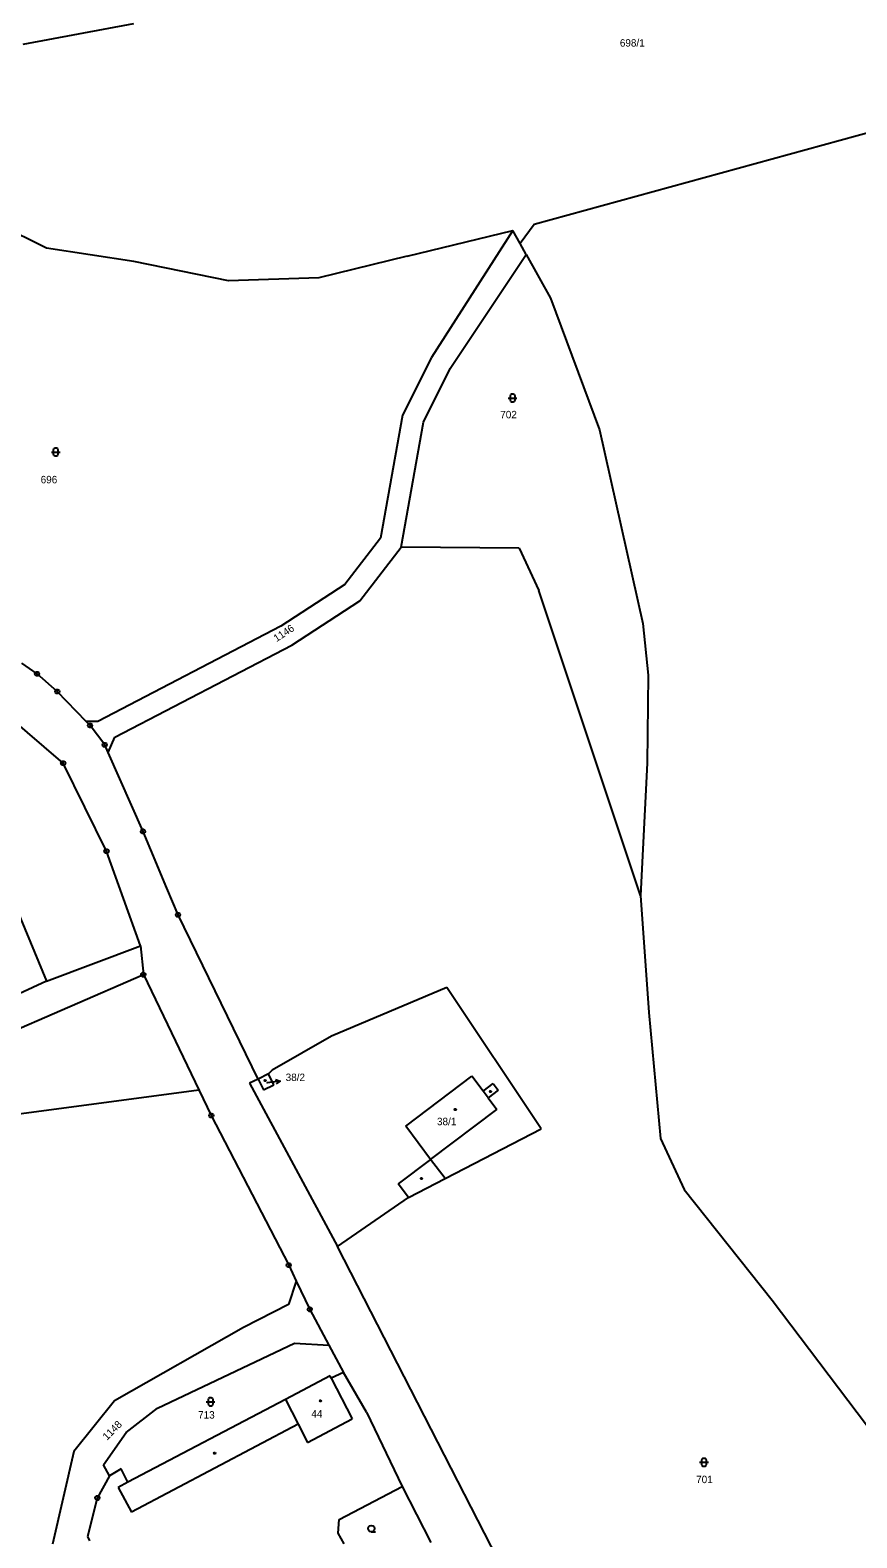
# Model space of a CAD drawing. Extents: x -812394 to -807601, y -1013098 to -1009266.
# Drawn here: x -809607.5 to -809418.3, y -1011158.1 to -1010813 of the extents above; entities that cross this region are included whole.
import ezdxf

# ---------------------------------------------------------------- set-up
doc = ezdxf.new("R2010")
doc.units = 0
for name, color, linetype in [('KN_HRANICE', 7, 'Continuous'), ('KN_KULTURY', 7, 'Continuous'), ('KN_MEZNIKY', 7, 'Continuous'), ('KN_PARCELY', 7, 'Continuous'), ('KN_SLUCKY', 7, 'Continuous'), ('KN_VEDENI', 7, 'Continuous')]:
    doc.layers.add(name, color=color, linetype=linetype)

# ---------------------------------------------------------------- blocks, each defined once
blk = doc.blocks.new('304')
blk.add_lwpolyline([(0, 0), (-0.38, 0.1), (-0.65, 0.37), (-0.75, 0.74), (-0.65, 1.11), (-0.38, 1.38), (-0.01, 1.48), (0.36, 1.38), (0.63, 1.11), (0.73, 0.73), (0.63, 0.35), (0.36, 0.08), (-0.02, -0.02), (0.98, -0.02)])
blk = doc.blocks.new('316')
for points in [[(-1, 1), (0.27, 1), (1, 1)], [(-0.5, 1.5), (-0.4, 1.79), (-0.15, 1.97), (0.16, 1.97), (0.41, 1.79), (0.51, 1.5), (0.51, 0.5), (0.41, 0.21), (0.16, 0.03), (-0.15, 0.03), (-0.4, 0.21), (-0.5, 0.5), (-0.5, 1.5)]]:
    blk.add_lwpolyline(points)
blk = doc.blocks.new('10292')
blk.add_line((0, 3), (0, 0))
blk.add_lwpolyline([(-0.5, 2), (0, 3), (0.5, 2)])
blk = doc.blocks.new('402')
blk.add_lwpolyline([(0.09, 0.15), (0.18, 0), (0.09, -0.15), (-0.09, -0.15), (-0.18, 0), (-0.09, 0.15), (0.09, 0.15)])
blk = doc.blocks.new('105')
blk.add_line((-0.12, 0), (0.12, 0))
blk.add_lwpolyline([(0.15, 0.48), (0.4, 0.3), (0.5, 0.01), (0.4, -0.28), (0.15, -0.46), (-0.16, -0.46), (-0.41, -0.28), (-0.51, 0.01), (-0.41, 0.3), (-0.16, 0.48), (0.15, 0.48)])

msp = doc.modelspace()

# ---------------------------------------------------------------- linework, layer by layer
at = {"layer": 'KN_HRANICE'}
for p, q in [((-809609.07, -1010816.23), (-809583.77, -1010811.56)), ((-809359.87, -1010821.19), (-809492.16, -1010857.54)), ((-809492.16, -1010857.54), (-809495.34, -1010861.89)), ((-809521.17, -1010864.79), (-809497.02, -1010858.87)), ((-809497.02, -1010858.87), (-809515.67, -1010887.99)), ((-809495.34, -1010861.89), (-809497.02, -1010858.87)), ((-809511.33, -1010890.51), (-809493.94, -1010864.41)), ((-809493.94, -1010864.41), (-809495.34, -1010861.89)), ((-809493.94, -1010864.41), (-809488.39, -1010874.4)), ((-809488.39, -1010874.4), (-809477.19, -1010904.54)), ((-809515.67, -1010887.99), (-809522.26, -1010901.18)), ((-809517.46, -1010902.78), (-809511.33, -1010890.51)), ((-809522.26, -1010901.18), (-809527.3, -1010929.3)), ((-809522.6, -1010931.38), (-809517.46, -1010902.78)), ((-809477.19, -1010904.54), (-809467.29, -1010948.86)), ((-809527.3, -1010929.3), (-809535.47, -1010939.93)), ((-809532.02, -1010943.65), (-809522.6, -1010931.38)), ((-809495.6, -1010931.58), (-809522.6, -1010931.38)), ((-809495.6, -1010931.58), (-809491.07, -1010941.26)), ((-809535.47, -1010939.93), (-809550.11, -1010949.47)), ((-809547.59, -1010953.79), (-809532.02, -1010943.65)), ((-809467.79, -1011011.05), (-809491.07, -1010941.26)), ((-809550.11, -1010949.47), (-809592, -1010971.27)), ((-809467.29, -1010948.86), (-809466.07, -1010960.63)), ((-809588.08, -1010974.86), (-809547.59, -1010953.79)), ((-809605.9, -1010960.37), (-809609.36, -1010957.92)), ((-809601.27, -1010964.41), (-809605.9, -1010960.37)), ((-809466.07, -1010960.63), (-809466.29, -1010980.8)), ((-809594.67, -1010971.27), (-809601.27, -1010964.41)), ((-809599.93, -1010980.8), (-809612.44, -1010970.06)), ((-809592, -1010971.27), (-809594.67, -1010971.27)), ((-809593.78, -1010972.2), (-809594.67, -1010971.27)), ((-809590.43, -1010976.6), (-809593.78, -1010972.2)), ((-809589.65, -1010978.35), (-809588.08, -1010974.86)), ((-809589.65, -1010978.35), (-809590.43, -1010976.6)), ((-809581.65, -1010996.4), (-809589.65, -1010978.35)), ((-809590.02, -1011000.93), (-809599.93, -1010980.8)), ((-809466.29, -1010980.8), (-809467.79, -1011011.05)), ((-809579.89, -1011000.6), (-809581.65, -1010996.4)), ((-809582.24, -1011022.59), (-809590.02, -1011000.93)), ((-809576.22, -1011009.38), (-809579.89, -1011000.6)), ((-809573.65, -1011015.51), (-809576.22, -1011009.38)), ((-809612.38, -1011009.85), (-809603.78, -1011030.67)), ((-809467.79, -1011011.05), (-809465.93, -1011037.86)), ((-809555.27, -1011053.13), (-809573.65, -1011015.51)), ((-809603.78, -1011030.67), (-809582.24, -1011022.59)), ((-809582.24, -1011022.59), (-809581.58, -1011029.19)), ((-809638.37, -1011053.74), (-809581.58, -1011029.19)), ((-809581.58, -1011029.19), (-809566.04, -1011061.41)), ((-809603.78, -1011030.67), (-809652.22, -1011053.19)), ((-809512.1, -1011032.11), (-809538.56, -1011043.3)), ((-809490.52, -1011064.5), (-809512.1, -1011032.11)), ((-809465.93, -1011037.86), (-809463.23, -1011066.67)), ((-809538.56, -1011043.3), (-809552.1, -1011051.08)), ((-809555.27, -1011053.13), (-809557.26, -1011054.05)), ((-809557.26, -1011054.05), (-809537.18, -1011091.39)), ((-809552.91, -1011051.92), (-809555.27, -1011053.13)), ((-809555.27, -1011053.13), (-809554.09, -1011055.53)), ((-809552.1, -1011051.08), (-809552.91, -1011051.92)), ((-809551.74, -1011054.37), (-809552.91, -1011051.92)), ((-809554.09, -1011055.53), (-809551.74, -1011054.37)), ((-809566.04, -1011061.41), (-809548.3, -1011095.68)), ((-809512.53, -1011075.85), (-809490.52, -1011064.5)), ((-809463.23, -1011066.67), (-809457.81, -1011078.32)), ((-809520.92, -1011080.18), (-809512.53, -1011075.85)), ((-809457.81, -1011078.32), (-809437.7, -1011103.69)), ((-809537.18, -1011091.39), (-809520.92, -1011080.18)), ((-809488.8, -1011185.67), (-809537.18, -1011091.39)), ((-809548.3, -1011095.68), (-809546.58, -1011099.3)), ((-809546.58, -1011099.3), (-809548.34, -1011104.67)), ((-809546.58, -1011099.3), (-809543.49, -1011105.78)), ((-809548.34, -1011104.67), (-809558.67, -1011109.91)), ((-809543.49, -1011105.78), (-809539.11, -1011114.01)), ((-809437.7, -1011103.69), (-809413.98, -1011135.02)), ((-809558.67, -1011109.91), (-809588.2, -1011126.73)), ((-809578.32, -1011128.41), (-809547.02, -1011113.55)), ((-809547.02, -1011113.55), (-809539.11, -1011114.01)), ((-809539.11, -1011114.01), (-809535.79, -1011120.25)), ((-809538.86, -1011121.02), (-809549.05, -1011126.42)), ((-809538.57, -1011121.56), (-809538.86, -1011121.02)), ((-809535.79, -1011120.25), (-809538.57, -1011121.56)), ((-809530.55, -1011129.29), (-809535.79, -1011120.25)), ((-809588.2, -1011126.73), (-809597.5, -1011138.33)), ((-809549.05, -1011126.42), (-809585.1, -1011145.33)), ((-809585.5, -1011133.94), (-809578.32, -1011128.41)), ((-809530.55, -1011129.29), (-809522.34, -1011146.29)), ((-809590.73, -1011141.36), (-809585.5, -1011133.94)), ((-809597.5, -1011138.33), (-809602.41, -1011159.55)), ((-809589.35, -1011143.88), (-809592.13, -1011148.96)), ((-809589.35, -1011143.88), (-809590.73, -1011141.36)), ((-809586.68, -1011142.26), (-809589.35, -1011143.88)), ((-809585.1, -1011145.33), (-809586.68, -1011142.26)), ((-809536.8, -1011153.9), (-809522.34, -1011146.29)), ((-809522.34, -1011146.29), (-809515.79, -1011159.15)), ((-809592.13, -1011148.96), (-809594.38, -1011157.78)), ((-809536.98, -1011157.02), (-809536.8, -1011153.9)), ((-809594.38, -1011157.78), (-809593.87, -1011158.76)), ((-809535.65, -1011159.47), (-809536.98, -1011157.02))]:
    msp.add_line(p, q, dxfattribs=at)
msp.add_lwpolyline([(-809521.17, -1010864.79), (-809541.42, -1010869.76), (-809562.13, -1010870.38), (-809583.78, -1010865.98), (-809603.73, -1010862.94), (-809614.59, -1010857.61)], dxfattribs=at)
at = {"layer": 'KN_PARCELY'}
msp.add_line((-809553.32, -1011053.95), (-809553.22, -1011053.94), dxfattribs=at)
at = {"layer": 'KN_SLUCKY'}
for p, q in [((-809521.54, -1011063.88), (-809506.4, -1011052.38)), ((-809503.81, -1011055.83), (-809506.4, -1011052.38)), ((-809503.81, -1011055.83), (-809501.5, -1011054.09)), ((-809501.5, -1011054.09), (-809500.35, -1011055.62)), ((-809502.67, -1011057.36), (-809503.81, -1011055.83)), ((-809500.35, -1011055.62), (-809502.67, -1011057.36)), ((-809502.67, -1011057.36), (-809500.67, -1011060.02)), ((-809515.83, -1011071.47), (-809500.67, -1011060.02)), ((-809515.83, -1011071.47), (-809521.54, -1011063.88)), ((-809515.83, -1011071.47), (-809523.25, -1011077.08)), ((-809512.53, -1011075.85), (-809515.83, -1011071.47)), ((-809520.92, -1011080.18), (-809523.25, -1011077.08)), ((-809538.57, -1011121.56), (-809533.76, -1011130.86)), ((-809549.05, -1011126.42), (-809546.14, -1011132.09)), ((-809546.14, -1011132.09), (-809584.26, -1011152.23)), ((-809546.14, -1011132.09), (-809544, -1011136.27)), ((-809544, -1011136.27), (-809533.76, -1011130.86)), ((-809585.1, -1011145.33), (-809587.34, -1011146.52)), ((-809587.34, -1011146.52), (-809584.26, -1011152.23))]:
    msp.add_line(p, q, dxfattribs=at)
at = {"layer": 'KN_VEDENI'}
msp.add_lwpolyline([(-809723.95, -1011075.51), (-809718.84, -1011074.89), (-809662.06, -1011067.52), (-809614.03, -1011061.6), (-809568.87, -1011055.54)], dxfattribs=at)

# ---------------------------------------------------------------- block references
at = {"layer": 'KN_KULTURY'}
for name, p in [('316', (-809497.08, -1010898.24)), ('316', (-809601.64, -1010910.6)), ('402', (-809553.71, -1011053.39)), ('402', (-809502.12, -1011055.9)), ('402', (-809510.19, -1011060.07)), ('402', (-809517.95, -1011075.83)), ('316', (-809566.2, -1011127.93)), ('402', (-809541.04, -1011126.74)), ('402', (-809565.26, -1011138.71)), ('316', (-809453.28, -1011141.77)), ('304', (-809529.42, -1011156.69))]:
    msp.add_blockref(name, p, dxfattribs=at)
at = {"layer": 'KN_MEZNIKY'}
for p in [(-809605.9, -1010960.37), (-809601.27, -1010964.41), (-809593.78, -1010972.2), (-809590.43, -1010976.6), (-809599.93, -1010980.8), (-809581.65, -1010996.4), (-809590.02, -1011000.93), (-809573.65, -1011015.51), (-809581.58, -1011029.19), (-809566.04, -1011061.41), (-809548.3, -1011095.68), (-809543.49, -1011105.78), (-809592.13, -1011148.96)]:
    msp.add_blockref('105', p, dxfattribs=at)
at = {"layer": 'KN_PARCELY', "rotation": -82.23006099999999}
msp.add_blockref('10292', (-809553.22, -1011053.94), dxfattribs=at)

# ---------------------------------------------------------------- texts
at = {"layer": 'KN_PARCELY'}
for s, height, p in [('698/1', 1.7, (-809472.53, -1010816.81)), ('702', 1.7, (-809499.9, -1010901.87)), ('696', 1.7, (-809605.08, -1010916.74)), ('38/2', 0.1, (-809553.52, -1011053.95)), ('38/2', 1.7, (-809549.01, -1011053.53)), ('38/1', 1.7, (-809514.38, -1011063.64)), ('713', 1.7, (-809569.05, -1011130.78)), ('44', 1.7, (-809543.13, -1011130.53)), ('701', 1.7, (-809455.07, -1011145.55))]:
    msp.add_text(s, height=height, dxfattribs=at).set_placement(p)
for s, rotation, p in [('1146', 33.289, (-809551.1, -1010953.11)), ('1148', 44.863, (-809589.9, -1011135.85))]:
    msp.add_text(s, height=1.7, rotation=rotation, dxfattribs=at).set_placement(p)

doc.saveas('drawing.dxf')
